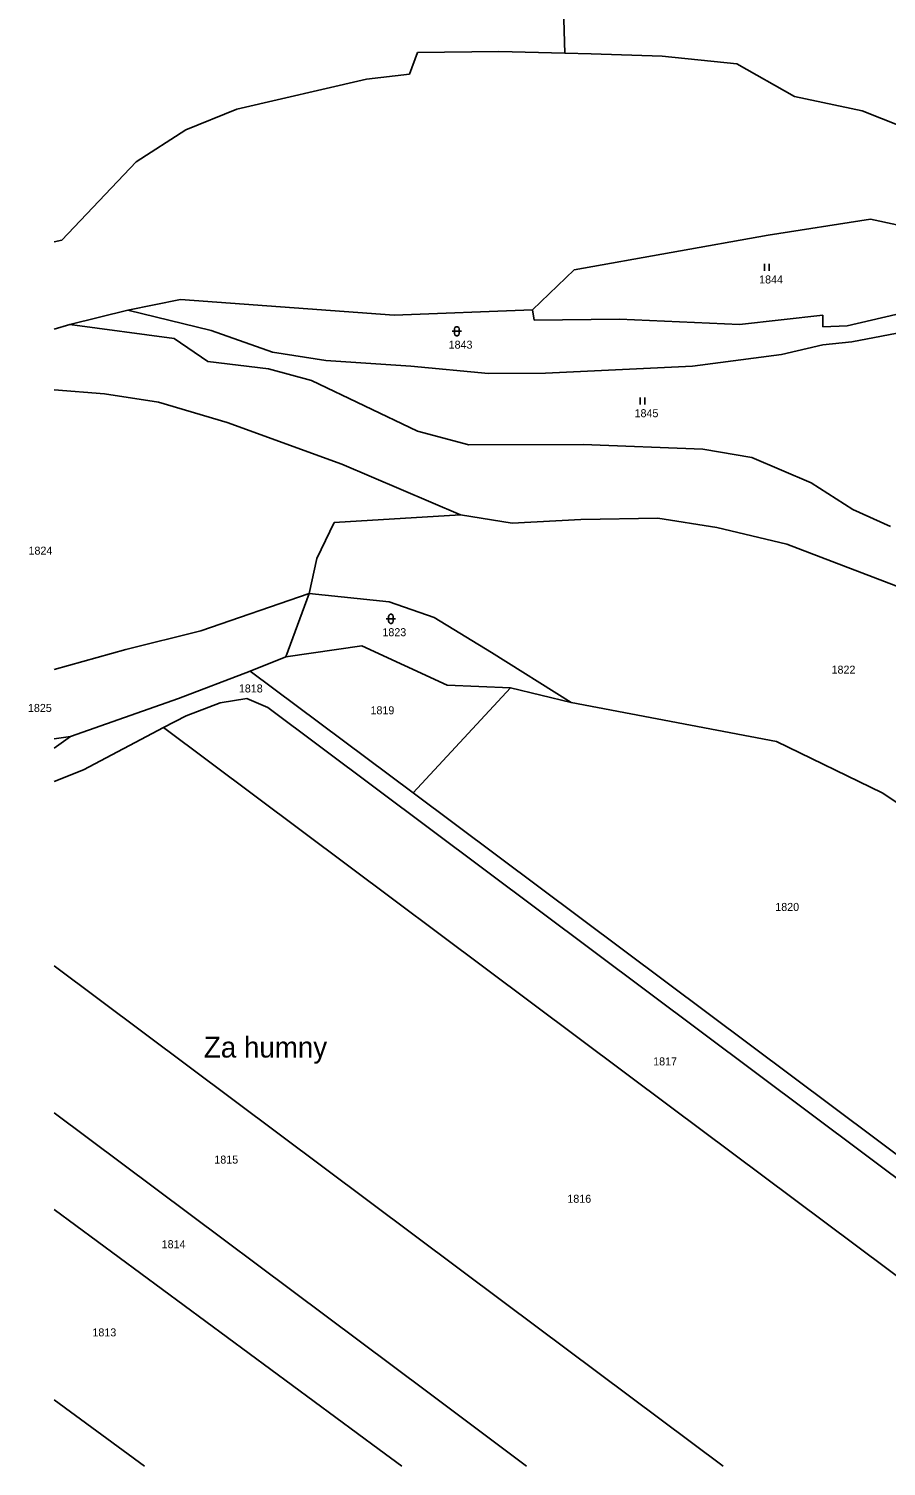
# Model space of a CAD drawing. Extents: x -801853 to -800578, y -1017479 to -1016338.
# Drawn here: x -801853.4 to -801671.4, y -1017477.7 to -1017172.4 of the extents above; entities that cross this region are included whole.
import ezdxf

# ---------------------------------------------------------------- set-up
doc = ezdxf.new("R2010")
doc.units = 0
for name, color, linetype in [('Default', 7, 'Continuous'), ('KN_HRANICE', 7, 'Continuous'), ('KN_KULTURY', 7, 'Continuous'), ('KN_PARCELY', 7, 'Continuous')]:
    doc.layers.add(name, color=color, linetype=linetype)

# ---------------------------------------------------------------- blocks, each defined once
blk = doc.blocks.new('306')
at = {"layer": 'Default'}
for p, q in [((-0.5, 1.5), (-0.5, 0)), ((0.5, 0), (0.5, 1.5))]:
    blk.add_line(p, q, dxfattribs=at)
blk = doc.blocks.new('316')
at = {"layer": 'Default'}
for points in [[(-1, 1), (0.27, 1), (1, 1)], [(-0.5, 1.5), (-0.4, 1.79), (-0.15, 1.97), (0.16, 1.97), (0.41, 1.79), (0.51, 1.5), (0.51, 0.5), (0.41, 0.21), (0.16, 0.03), (-0.15, 0.03), (-0.4, 0.21), (-0.5, 0.5), (-0.5, 1.5)]]:
    blk.add_lwpolyline(points, dxfattribs=at)

msp = doc.modelspace()

# ---------------------------------------------------------------- linework, layer by layer
at = {"layer": 'KN_HRANICE'}
for p, q in [((-801739.66, -1017177.55), (-801740.19, -1017157.87)), ((-801753.68, -1017177.19), (-801770.92, -1017177.42)), ((-801739.66, -1017177.55), (-801753.68, -1017177.19)), ((-801770.92, -1017177.42), (-801772.63, -1017182.03)), ((-801734.03, -1017177.69), (-801739.66, -1017177.55)), ((-801718.95, -1017178.17), (-801734.03, -1017177.69)), ((-801703.12, -1017179.81), (-801718.95, -1017178.17)), ((-801690.89, -1017186.76), (-801703.12, -1017179.81)), ((-801781.73, -1017183.09), (-801809.26, -1017189.42)), ((-801772.63, -1017182.03), (-801781.73, -1017183.09)), ((-801809.26, -1017189.42), (-801820.06, -1017193.82)), ((-801676.49, -1017189.78), (-801690.89, -1017186.76)), ((-801664.54, -1017194.54), (-801676.49, -1017189.78)), ((-801820.06, -1017193.82), (-801830.66, -1017200.64)), ((-801830.66, -1017200.64), (-801846.4, -1017217.27)), ((-801674.74, -1017212.79), (-801696.47, -1017216.21)), ((-801659.71, -1017216.08), (-801674.74, -1017212.79)), ((-801696.47, -1017216.21), (-801737.67, -1017223.58)), ((-801846.4, -1017217.27), (-801848.02, -1017217.6)), ((-801737.67, -1017223.58), (-801746.49, -1017232.05)), ((-801832.4, -1017232.1), (-801844.73, -1017235.18)), ((-801821.2, -1017229.84), (-801832.4, -1017232.1)), ((-801832.4, -1017232.1), (-801814.72, -1017236.46)), ((-801775.86, -1017233.2), (-801821.2, -1017229.84)), ((-801746.49, -1017232.05), (-801775.86, -1017233.2)), ((-801746.49, -1017232.05), (-801746.17, -1017234.23)), ((-801844.73, -1017235.18), (-801848.02, -1017236.16)), ((-801844.73, -1017235.18), (-801822.6, -1017238.12)), ((-801746.17, -1017234.23), (-801728, -1017234.04)), ((-801728, -1017234.04), (-801702.59, -1017235.15)), ((-801702.59, -1017235.15), (-801684.84, -1017233.15)), ((-801684.84, -1017233.15), (-801684.86, -1017235.67)), ((-801679.68, -1017235.48), (-801669.39, -1017233.06)), ((-801822.6, -1017238.12), (-801815.41, -1017243.02)), ((-801814.72, -1017236.46), (-801801.72, -1017241.07)), ((-801684.86, -1017235.67), (-801679.68, -1017235.48)), ((-801678.68, -1017238.81), (-801666.12, -1017236.42)), ((-801801.72, -1017241.07), (-801790.4, -1017242.78)), ((-801693.67, -1017241.51), (-801684.86, -1017239.45)), ((-801684.86, -1017239.45), (-801678.68, -1017238.81)), ((-801815.41, -1017243.02), (-801802.54, -1017244.57)), ((-801790.4, -1017242.78), (-801772.32, -1017243.99)), ((-801772.32, -1017243.99), (-801755.83, -1017245.57)), ((-801743.74, -1017245.48), (-801712.51, -1017244.02)), ((-801712.51, -1017244.02), (-801693.67, -1017241.51)), ((-801802.54, -1017244.57), (-801793.4, -1017247.04)), ((-801793.4, -1017247.04), (-801770.93, -1017257.82)), ((-801755.83, -1017245.57), (-801743.74, -1017245.48)), ((-801837.36, -1017249.87), (-801848.02, -1017249.05)), ((-801825.91, -1017251.69), (-801837.36, -1017249.87)), ((-801811.34, -1017255.97), (-801825.91, -1017251.69)), ((-801787.01, -1017264.79), (-801811.34, -1017255.97)), ((-801770.93, -1017257.82), (-801760.04, -1017260.74)), ((-801760.04, -1017260.74), (-801735.74, -1017260.62)), ((-801735.74, -1017260.62), (-801710.32, -1017261.66)), ((-801710.32, -1017261.66), (-801699.91, -1017263.42)), ((-801761.76, -1017275.57), (-801787.01, -1017264.79)), ((-801699.91, -1017263.42), (-801687.36, -1017268.82)), ((-801687.36, -1017268.82), (-801678.51, -1017274.48)), ((-801678.51, -1017274.48), (-801670.52, -1017278.09)), ((-801792.26, -1017284.84), (-801788.6, -1017277.18)), ((-801788.6, -1017277.18), (-801761.76, -1017275.57)), ((-801750.82, -1017277.33), (-801761.76, -1017275.57)), ((-801736.26, -1017276.56), (-801750.82, -1017277.33)), ((-801719.86, -1017276.29), (-801736.26, -1017276.56)), ((-801707.38, -1017278.31), (-801719.86, -1017276.29)), ((-801692.48, -1017281.81), (-801707.38, -1017278.31)), ((-801658.95, -1017294.66), (-801692.48, -1017281.81)), ((-801793.91, -1017292.28), (-801792.26, -1017284.84)), ((-801816.89, -1017300.2), (-801793.91, -1017292.28)), ((-801793.91, -1017292.28), (-801798.84, -1017305.74)), ((-801793.91, -1017292.28), (-801776.93, -1017294.07)), ((-801776.93, -1017294.07), (-801767.36, -1017297.41)), ((-801767.36, -1017297.41), (-801755.22, -1017304.85)), ((-801832.86, -1017304.19), (-801816.89, -1017300.2)), ((-801848.02, -1017308.46), (-801832.86, -1017304.19)), ((-801798.84, -1017305.74), (-801782.7, -1017303.4)), ((-801782.7, -1017303.4), (-801764.64, -1017311.74)), ((-801755.22, -1017304.85), (-801738.31, -1017315.47)), ((-801806.42, -1017308.77), (-801798.84, -1017305.74)), ((-801821.66, -1017314.59), (-801806.42, -1017308.77)), ((-801806.42, -1017308.77), (-801771.82, -1017334.66)), ((-801844.56, -1017322.69), (-801821.66, -1017314.59)), ((-801812.8, -1017315.49), (-801807.12, -1017314.59)), ((-801807.12, -1017314.59), (-801802.71, -1017316.54)), ((-801771.82, -1017334.66), (-801751.14, -1017312.3)), ((-801764.64, -1017311.74), (-801751.14, -1017312.3)), ((-801751.14, -1017312.3), (-801738.31, -1017315.47)), ((-801820.01, -1017318.24), (-801812.8, -1017315.49)), ((-801802.71, -1017316.54), (-801653.38, -1017428.3)), ((-801694.67, -1017323.74), (-801738.31, -1017315.47)), ((-801841.82, -1017329.72), (-801824.8, -1017320.76)), ((-801824.8, -1017320.76), (-801820.01, -1017318.24)), ((-801824.8, -1017320.76), (-801717.22, -1017401.3)), ((-801848.02, -1017325.12), (-801844.56, -1017322.69)), ((-801844.56, -1017322.69), (-801848.02, -1017323.17)), ((-801672.29, -1017334.66), (-801694.67, -1017323.74)), ((-801848.02, -1017332.24), (-801841.82, -1017329.72)), ((-801771.82, -1017334.66), (-801650.93, -1017425.14)), ((-801672.29, -1017334.66), (-801607.17, -1017377.34)), ((-801848.02, -1017371.37), (-801752.52, -1017442.84)), ((-801848.02, -1017402.62), (-801768.75, -1017461.94)), ((-801717.22, -1017401.3), (-801615.2, -1017477.65)), ((-801848.02, -1017423.14), (-801779.08, -1017474.09)), ((-801752.52, -1017442.84), (-801706.01, -1017477.65)), ((-801848.02, -1017463.54), (-801828.88, -1017477.65)), ((-801768.75, -1017461.94), (-801747.76, -1017477.65)), ((-801779.08, -1017474.09), (-801774.26, -1017477.65))]:
    msp.add_line(p, q, dxfattribs=at)

# ---------------------------------------------------------------- block references
at = {"layer": 'KN_KULTURY'}
for name, p in [('306', (-801696.73, -1017223.75)), ('316', (-801762.56, -1017237.6)), ('306', (-801723.13, -1017252.15)), ('316', (-801776.56, -1017298.66))]:
    msp.add_blockref(name, p, dxfattribs=at)

# ---------------------------------------------------------------- texts
at = {"layer": 'KN_PARCELY'}
for s, height, p in [('1844', 1.7, (-801698.39, -1017226.45)), ('1843', 1.7, (-801764.3, -1017240.3)), ('1845', 1.7, (-801724.83, -1017254.85)), ('1824', 1.7, (-801853.49, -1017284.04)), ('1823', 1.7, (-801778.36, -1017301.36)), ('1822', 1.7, (-801683.01, -1017309.32)), ('1818', 1.7, (-801808.83, -1017313.31)), ('1825', 1.7, (-801853.61, -1017317.45)), ('1819', 1.7, (-801780.89, -1017317.95)), ('1820', 1.7, (-801694.96, -1017359.71)), ('Za humny', 4.4, (-801816.26, -1017390.85)), ('1817', 1.7, (-801720.88, -1017392.52)), ('1815', 1.7, (-801814.04, -1017413.37)), ('1816', 1.7, (-801739.1, -1017421.69)), ('1814', 1.7, (-801825.22, -1017431.34)), ('1813', 1.7, (-801839.92, -1017450.07))]:
    msp.add_text(s, height=height, dxfattribs=at).set_placement(p)

doc.saveas('drawing.dxf')
